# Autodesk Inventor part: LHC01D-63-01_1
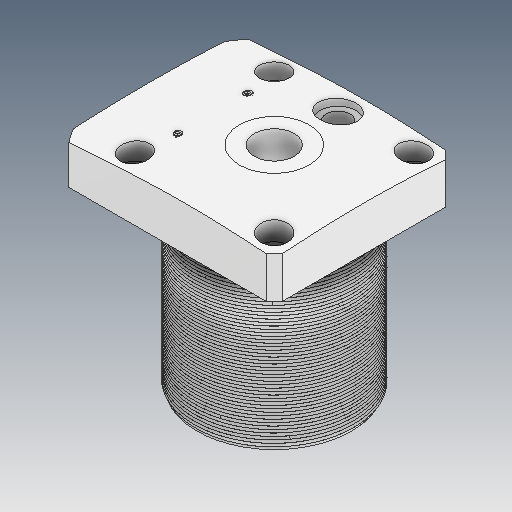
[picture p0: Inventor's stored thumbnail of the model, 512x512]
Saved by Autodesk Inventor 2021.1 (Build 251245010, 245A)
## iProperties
Created: 2021-06
Part Number: LHC01D-63-01_1
Material: Ogólny
Document SubType Name: Modeling
Designer: user
Density: 1 g/cm^3
Appearance: Domyślna
Author: user
Revision Number: ÈÎºÎ
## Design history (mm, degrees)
feature "ÊäÈë1"
feature "ÊäÈë2"
feature "NONE" [ÊäÈë]
node "Bryła1"
node "Bryła2"
node "Bryła3"
